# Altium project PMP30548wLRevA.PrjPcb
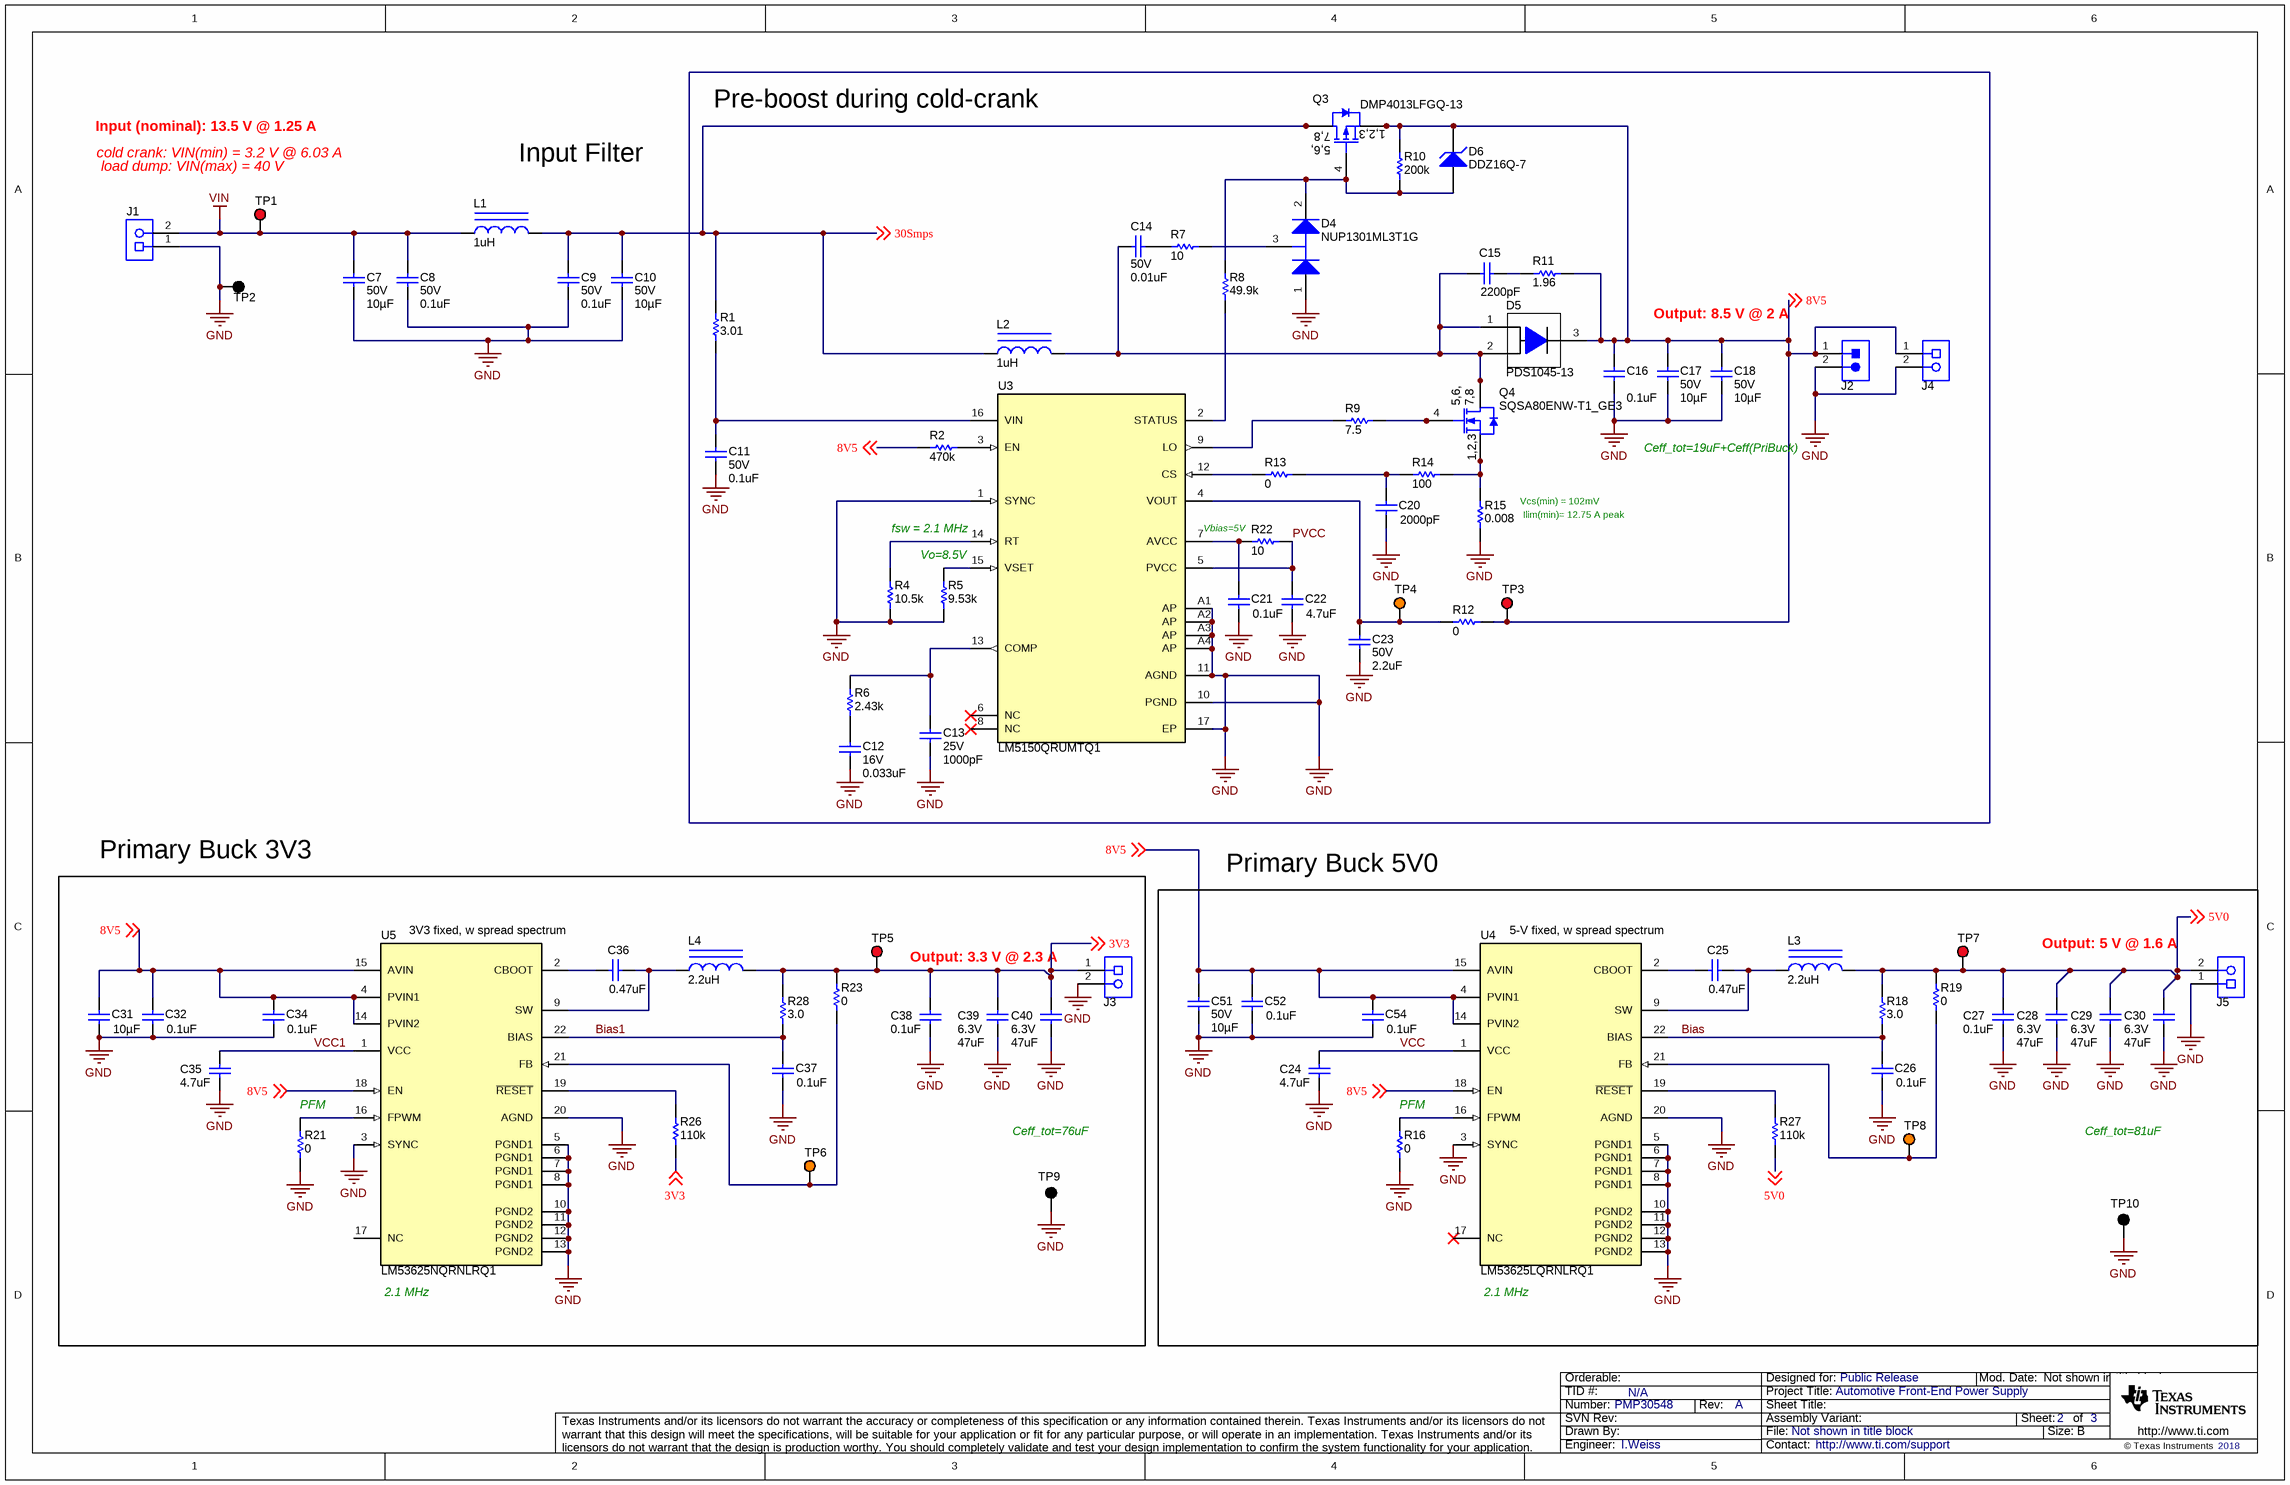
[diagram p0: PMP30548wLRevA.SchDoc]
TID: N/A; TechSupport: http://www.ti.com/support; SCH_Rev: A; PRJ_Title: Automotive Front-End Power Supply; PRJ_Number: PMP30548; PRJ_Engineer: I.Weiss; PRJ_Customer: Public Release; PCB_Rev: A; PCB_Layout: I.Weiss; CopyrightYear: 2018
2 sheets, 101 parts. Net scope: global (net labels, ports and power ports of the same name join across sheets).
Board file: PMP30548wLRevA.PcbDoc
Sheets:
  PMP30548wLRevA.SchDoc
  PMP30548wLRevA_Hardware.SchDoc

## Sheet PMP30548wLRevA.SchDoc
size 431 x 279 mm; Date: Not shown in title block; ApprovedBy: Not shown in title block; CheckedBy: Not shown in title block; Author: Not shown in title block; CompanyName: Not shown in title block; Engineer: Not shown in title block; Organization: Not shown in title block; Address1: Not shown in title block; Address2: Not shown in title block; Address3: Not shown in title block; Address4: Not shown in title block; DocumentNumber: 1; Revision: Use project parameter SCH_Rev; SheetNumber: 2; SheetTotal: 3; PageSetup: Record=PageOptions¦CenterHorizontal=True¦CenterVertical=True¦PrintScale=1.00¦XCorrection=1.00¦YCorrection=1.00¦PrintKind=0¦BorderSize=5000000¦LeftOffset=0¦BottomOffset=0¦Orientation=2¦PaperLength=1000¦PaperWidth=1000¦Scale=100¦PaperSource=15¦PrintQuality=600¦MediaType=1¦DitherType=10¦PaperKind=Letter¦PrintScaleMode=1

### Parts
C7  VDC_V: 50V  ValueDisplayed: 10µF  [1210_280]  (hidden comment: GRJ32ER71H106KE11L)
C8  VDC_V: 50V  ValueDisplayed: 0.1uF  [0603]  (hidden comment: GRM188R71H104KA93D)
C9  VDC_V: 50V  ValueDisplayed: 0.1uF  [0603]  (hidden comment: GRM188R71H104KA93D)
C10  VDC_V: 50V  ValueDisplayed: 10µF  [1210_280]  (hidden comment: GRJ32ER71H106KE11L)
C11  VDC_V: 50V  ValueDisplayed: 0.1uF  [0603]  (hidden comment: GRM188R71H104KA93D)
C12  VDC_V: 16V  ValueDisplayed: 0.033uF  [0402]  (hidden comment: GRM155R71C333KA01D)
C13  VDC_V: 25V  ValueDisplayed: 1000pF  [0402]  (hidden comment: C0402C102J3RACTU)
C14  VDC_V: 50V  ValueDisplayed: 0.01uF  [0402]  (hidden comment: GRM155R71H103KA88D)
C15  ValueDisplayed: 2200pF  [0402]  (hidden comment: GRM155R71H222KA01D)
C16  ValueDisplayed: 0.1uF  [0603]  (hidden comment: GRM188R71H104KA93D)
C17  VDC_V: 50V  ValueDisplayed: 10µF  [1210_280]  (hidden comment: GRJ32ER71H106KE11L)
C18  VDC_V: 50V  ValueDisplayed: 10µF  [1210_280]  (hidden comment: GRJ32ER71H106KE11L)
C20  ValueDisplayed: 2000pF  [0603]  (hidden comment: GRM188R71H202KA01D)
C21  ValueDisplayed: 0.1uF  [0603]  (hidden comment: GRM188R71H104KA93D)
C22  ValueDisplayed: 4.7uF  [0805_HV]  (hidden comment: 885012207025)
C23  VDC_V: 50V  ValueDisplayed: 2.2uF  [1206_180]  (hidden comment: C3216X7R1H225K160AB)
C24  ValueDisplayed: 4.7uF  [0805_HV]  (hidden comment: 885012207025)
C25  ValueDisplayed: 0.47uF  [0603]  (hidden comment: GRM188R71E474KA12D)
C26  ValueDisplayed: 0.1uF  [0603]  (hidden comment: GRM188R71H104KA93D)
C27  ValueDisplayed: 0.1uF  [0603]  (hidden comment: GRM188R71H104KA93D)
C28  VDC_V: 6.3V  ValueDisplayed: 47uF  [1210_280]  (hidden comment: GCM32ER70J476ME19L)
C29  VDC_V: 6.3V  ValueDisplayed: 47uF  [1210_280]  (hidden comment: GCM32ER70J476ME19L)
C30  VDC_V: 6.3V  ValueDisplayed: 47uF  [1210_280]  (hidden comment: GCM32ER70J476ME19L)
C31  ValueDisplayed: 10µF  [1210_280]  (hidden comment: GRJ32ER71H106KE11L)
C32  ValueDisplayed: 0.1uF  [0603]  (hidden comment: GRM188R71H104KA93D)
C34  ValueDisplayed: 0.1uF  [0603]  (hidden comment: GRM188R71H104KA93D)
C35  ValueDisplayed: 4.7uF  [0805_HV]  (hidden comment: 885012207025)
C36  ValueDisplayed: 0.47uF  [0603]  (hidden comment: GRM188R71E474KA12D)
C37  ValueDisplayed: 0.1uF  [0603]  (hidden comment: GRM188R71H104KA93D)
C38  ValueDisplayed: 0.1uF  [0603]  (hidden comment: GRM188R71H104KA93D)
C39  VDC_V: 6.3V  ValueDisplayed: 47uF  [1210_280]  (hidden comment: GCM32ER70J476ME19L)
C40  VDC_V: 6.3V  ValueDisplayed: 47uF  [1210_280]  (hidden comment: GCM32ER70J476ME19L)
C51  VDC_V: 50V  ValueDisplayed: 10µF  [1210_280]  (hidden comment: GRJ32ER71H106KE11L)
C52  ValueDisplayed: 0.1uF  [0603]  (hidden comment: GRM188R71H104KA93D)
C54  ValueDisplayed: 0.1uF  [0603]  (hidden comment: GRM188R71H104KA93D)
D4  NUP1301ML3T1G  [SOT-23]
D5  PDS1045-13  [POWERDI5]
D6  DDZ16Q-7  [SOD-123]
J1  691411510002  [Wurth_691411510002]  (value not drawn)
J2  PBC02SAAN  [Sullins_PBC02SAAN]  (value not drawn)
J3  691411510002  [Wurth_691411510002]  (value not drawn)
J4  691411510002  [Wurth_691411510002]  (value not drawn)
J5  691411510002  [Wurth_691411510002]  (value not drawn)
L1  ValueDisplayed: 1uH  [IHLP-2525CZ]  (hidden comment: IHLP2525CZER1R0M01)
L2  ValueDisplayed: 1uH  [IHLP-2525CZ]  (hidden comment: IHLP2525CZER1R0M01)
L3  ValueDisplayed: 2.2uH  [IHLP-1616BZ]  (hidden comment: IHLP1616BZER2R2M11)
L4  ValueDisplayed: 2.2uH  [IHLP-1616BZ]  (hidden comment: IHLP1616BZER2R2M11)
Q3  DMP4013LFGQ-13  [PowerDI3333-8]
Q4  SQSA80ENW-T1_GE3  [PowerPAK_1212-8]
R1  ValueDisplayed: 3.01  [0603]  (hidden comment: CRCW06033R01FKEA)
R2  ValueDisplayed: 470k  [0603]  (hidden comment: CRCW0603470KJNEA)
R4  ValueDisplayed: 10.5k  [0402]  (hidden comment: CRCW040210K5FKED)
R5  ValueDisplayed: 9.53k  [0603]  (hidden comment: RT0603BRD079K53L)
R6  ValueDisplayed: 2.43k  [0603]  (hidden comment: RG1608P-2431-B-T5)
R7  ValueDisplayed: 10  [0402]  (hidden comment: CRCW040210R0JNED)
R8  ValueDisplayed: 49.9k  [0603]  (hidden comment: CRCW060349K9FKEA)
R9  ValueDisplayed: 7.5  [0603]  (hidden comment: CRCW06037R50JNEA)
R10  ValueDisplayed: 200k  [0402]  (hidden comment: CRCW0402200KJNED)
R11  ValueDisplayed: 1.96  [0402]  (hidden comment: CRCW04021R96FKED)
R12  ValueDisplayed: 0  [0603]  (hidden comment: RCS06030000Z0EA)
R13  ValueDisplayed: 0  [0603]  (hidden comment: RCS06030000Z0EA)
R14  ValueDisplayed: 100  [0402]  (hidden comment: ERJ-2GEJ101X)
R15  ValueDisplayed: 0.008  [KRL2012]  (hidden comment: KRL2012M-R008-F-T1)
R16  ValueDisplayed: 0  [0402]  (hidden comment: CRCW04020000Z0EDHP)
R18  ValueDisplayed: 3.0  [0603]  (hidden comment: CRCW06033R00JNEA)
R19  ValueDisplayed: 0  [0402]  (hidden comment: CRCW04020000Z0EDHP)
R21  ValueDisplayed: 0  [0402]  (hidden comment: CRCW04020000Z0EDHP)
R22  ValueDisplayed: 10  [0603]  (hidden comment: CRCW060310R0JNEA)
R23  ValueDisplayed: 0  [0402]  (hidden comment: CRCW04020000Z0EDHP)
R26  ValueDisplayed: 110k  [0402]  (hidden comment: CRCW0402110KJNED)
R27  ValueDisplayed: 110k  [0402]  (hidden comment: CRCW0402110KJNED)
R28  ValueDisplayed: 3.0  [0603]  (hidden comment: CRCW06033R00JNEA)
TP1  5000  [Keystone5000]  (value not drawn)
TP2  5001  [Keystone5001]  (value not drawn)
TP3  5000  [Keystone5000]  (value not drawn)
TP4  5003  [Keystone5003]  (value not drawn)
TP5  5000  [Keystone5000]  (value not drawn)
TP6  5003  [Keystone5003]  (value not drawn)
TP7  5000  [Keystone5000]  (value not drawn)
TP8  5003  [Keystone5003]  (value not drawn)
TP9  5001  [Keystone5001]  (value not drawn)
TP10  5001  [Keystone5001]  (value not drawn)
U3  LM5150QRUMTQ1  [RUM0016C]
U4  LM53625LQRNLRQ1  [RNL0022A]
U5  LM53625NQRNLRQ1  [RNL0022A]

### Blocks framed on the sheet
Pre-boost during cold-crank: C11-C18 C20-C23 D4-D6 J2 J4 L2 Q3 Q4 R1 R2 R4-R15 R22 TP3 TP4 U3
Output: 3.3 V @ 2.3 A: C31 C32 C34-C40 J3 L4 R21 R23 R26 R28 TP5 TP6 TP9 U5
Output: 5 V @ 1.6 A: C24-C30 C51 C52 C54 J5 L3 R16 R18 R19 R27 TP7 TP8 TP10 U4

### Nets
GND: C7.2 C8.2 C9.2 C10.2 C11.2 C12.2 C13.2 C16.2 C17.2 C18.2 C20.2 C21.2 C22.2 C23.2 C24.2 C26.2 C27.2 C28.2 C29.2 C30.2 C31.2 C32.2 C34.2 C35.2 C37.2 C38.2 C39.2 C40.2 C51.2 C52.2 C54.2 D4.1(A) J1.1 J2.2 J3.2 J4.2 J5.1 R4.1 R5.1 R15.1 R16.1 R21.1 TP2.1 TP9.1 TP10.1 U3.1(SYNC) U3.10(PGND) U3.11(AGND) U3.17(EP) U3.A1(AP) U3.A2(AP) U3.A3(AP) U3.A4(AP) U4.3(SYNC) U4.5(PGND1) U4.6(PGND1) U4.7(PGND1) U4.8(PGND1) U4.10(PGND2) U4.11(PGND2) U4.12(PGND2) U4.13(PGND2) U4.20(AGND) U5.3(SYNC) U5.5(PGND1) U5.6(PGND1) U5.7(PGND1) U5.8(PGND1) U5.10(PGND2) U5.11(PGND2) U5.12(PGND2) U5.13(PGND2) U5.20(AGND)
VIN: C7.1 C8.1 J1.2 L1.1 TP1.1
3V3: C38.1 C39.1 C40.1 J3.1 L4.2 R23.2 R26.1 R28.2 TP5.1 ; off-sheet 3V3
5V0: C27.1 C28.1 C29.1 C30.1 J5.2 L3.2 R18.2 R19.2 R27.1 TP7.1 ; off-sheet 5V0
8V5: C16.1 C17.1 C18.1 C31.1 C32.1 C34.1 C51.1 C52.1 C54.1 D5.3(K) D6.1(K) J2.1 J4.1 Q3.1(S) Q3.2(S) Q3.3(S) R2.2 R10.2 R11.1 R12.1 TP3.1 U4.4(PVIN1) U4.14(PVIN2) U4.15(AVIN) U4.18(EN) U5.4(PVIN1) U5.14(PVIN2) U5.15(AVIN) U5.18(EN) ; off-sheet 8V5
30Smps: C9.1 C10.1 L1.2 L2.1 Q3.5(D) Q3.6(D) Q3.7(D) Q3.8(D) Q3.9(D) R1.2 ; off-sheet 30Smps
Bias: C26.1 R18.1 U4.22(BIAS)
Bias1: C37.1 R28.1 U5.22(BIAS)
PVCC: C22.1 R22.2 U3.5(PVCC)
VCC: C24.1 U4.1(VCC)
VCC1: C35.1 U5.1(VCC)
NetC11_1: C11.1 R1.1 U3.16(VIN)
NetC12_1: C12.1 R6.2
NetC13_1: C13.1 R6.1 U3.13(COMP)
NetC14_1: C14.1 C15.2 D5.1(A) D5.2(A) L2.2 Q4.5(D) Q4.6(D) Q4.7(D) Q4.8(D) Q4.9(D)
NetC14_2: C14.2 R7.2
NetC15_1: C15.1 R11.2
NetC20_1: C20.1 R13.1 R14.1
NetC21_1: C21.1 R22.1 U3.7(AVCC)
NetC23_1: C23.1 R12.2 TP4.1 U3.4(VOUT)
NetC25_1: C25.1 L3.1 U4.9(SW)
NetC25_2: C25.2 U4.2(CBOOT)
NetC36_1: C36.1 L4.1 U5.9(SW)
NetC36_2: C36.2 U5.2(CBOOT)
NetD4_2: D4.2(K) D6.2(A) Q3.4(G) R8.2 R10.1
NetD4_3: D4.3(C) R7.1
NetQ4_1: Q4.1(S) Q4.2(S) Q4.3(S) R14.2 R15.2
NetQ4_4: Q4.4(G) R9.2
NetR2_1: R2.1 U3.3(EN)
NetR4_2: R4.2 U3.14(RT)
NetR5_2: R5.2 U3.15(VSET)
NetR8_1: R8.1 U3.2(STATUS)
NetR9_1: R9.1 U3.9(LO)
NetR13_2: R13.2 U3.12(CS)
NetR16_2: R16.2 U4.16(FPWM)
NetR19_1: R19.1 TP8.1 U4.21(FB)
NetR21_2: R21.2 U5.16(FPWM)
NetR23_1: R23.1 TP6.1 U5.21(FB)
NetR26_2: R26.2 U5.19(~{RESET})
NetR27_2: R27.2 U4.19(~{RESET})

Not connected (* = marked no-connect by the designer): U3 6(NC)* 8(NC)*; U4 17(NC)*; U5 17(NC)

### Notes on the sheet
- load dump: VIN(max) = 40 V
- Input (nominal): 13.5 V @ 1.25 A
- cold crank: VIN(min) = 3.2 V @ 6.03 A
- Input Filter
- Output: 8.5 V @ 2 A
- (near R15) Vcs(min) = 102mV
- Ceff_tot=19uF+Ceff(PriBuck)
- (near U3) fsw = 2.1 MHz
- Vo=8.5V
- (near R22) Vbias=5V
- (near R15) Ilim(min)= 12.75 A peak
- Primary Buck 3V3
- Primary Buck 5V0
- 3V3 fixed, w spread spectrum
- 5-V fixed, w spread spectrum
- (near R21) PFM
- (near R16) PFM
- Ceff_tot=76uF
- Ceff_tot=81uF
- (near U5) 2.1 MHz
- (near U4) 2.1 MHz

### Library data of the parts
C7 C10 C17 C18 C51 = CMP-0081135-1: CAP, CERM, 10 µF, 50 V,+/- 10%, X7R, 1210; Manufacturer: MuRata; TaMin_C: -55°C; ESR_ohm: 1m; Polarized: N; SizeAreaWB_mm2: 14.7; Value1: 0.001 ohm; U/M: EA; Value: 10uF; TaMax_C: 125°C; SizeZ_mm: 2.8; SizeX_mm: 3.2; SizeY_mm: 2.5; Cap_Case: 1210; SizeArea_mm2: 8; CompType: Capacitor; AEC Category: Q200
C8 C9 C11 = CMP-0007434-4: CAP, CERM, 0.1 uF, 50 V, +/- 10%, X7R, 0603; Manufacturer: MuRata; TaMin_C: -55°C; Polarized: N; SizeAreaWB_mm2: 4.68; Value1: Unknown; U/M: EA; Value: 0.1uF; TaMax_C: 125°C; SizeZ_mm: 1; SizeX_mm: 1.6; SizeY_mm: 0.8; SizeArea_mm2: 1.28; CompType: Capacitor; Cap_F: 100nF; AEC Category: Q200
C12 = CMP-0006650-2: CAP, CERM, 0.033 uF, 16 V, +/- 10%, X7R, 0402; Manufacturer: MuRata; TaMin_C: -55°C; Polarized: N; SizeAreaWB_mm2: 3; Value1: Unknown; U/M: EA; TaMax_C: 125°C; SizeZ_mm: 0.6; SizeX_mm: 1; SizeY_mm: 0.5; Cap_F: 33nF; AEC Category: Q200
C13 = CMP-0006234-2: CAP, CERM, 1000 pF, 25 V, +/- 5%, X7R, 0402; Manufacturer: Kemet; TaMin_C: -55°C; Polarized: N; SizeAreaWB_mm2: 3; Value1: Unknown; U/M: EA; Value: 1000pF; TaMax_C: 125°C; SizeZ_mm: 0.6; SizeX_mm: 1; SizeY_mm: 0.5; Cap_F: 1nF; AEC Category: Q200
C14 = CMP-0006674-2: CAP, CERM, 0.01 uF, 50 V, +/- 10%, X7R, 0402; Manufacturer: MuRata; TaMin_C: -55°C; Polarized: N; SizeAreaWB_mm2: 3; Value1: Unknown; U/M: EA; Value: 0.01uF; TaMax_C: 125°C; SizeZ_mm: 0.6; SizeX_mm: 1; SizeY_mm: 0.5; Cap_F: 10nF; AEC Category: Q200
C15 = CMP-0006683-2: CAP, CERM, 2200 pF, 50 V, +/- 10%, X7R, 0402; Manufacturer: MuRata; TaMin_C: -55°C; Polarized: N; SizeAreaWB_mm2: 3; Value1: Unknown; U/M: EA; Value: 2200pF; TaMax_C: 125°C; SizeZ_mm: 0.6; SizeX_mm: 1; SizeY_mm: 0.5; Value2: 50V; CompType: Capacitor; Cap_F: 2.2nF; AEC Category: Q200
C16 C21 C26 C27 C32 C34 C37 C38 C52 C54 = CMP-0007434-4: CAP, CERM, 0.1 uF, 50 V, +/- 10%, X7R, 0603; Manufacturer: MuRata; TaMin_C: -55°C; Polarized: N; SizeAreaWB_mm2: 4.68; Value1: Unknown; U/M: EA; Value: 0.1uF; TaMax_C: 125°C; SizeZ_mm: 1; SizeX_mm: 1.6; SizeY_mm: 0.8; Value2: 50V; SizeArea_mm2: 1.28; CompType: Capacitor; Cap_F: 100nF; AEC Category: Q200
C20 = CMP-0007441-5: CAP, CERM, 2000 pF, 50 V, +/- 10%, X7R, 0603; Manufacturer: MuRata; TaMin_C: -55°C; Polarized: N; SizeAreaWB_mm2: 4.68; Value1: Unknown; U/M: EA; Value: 2000pF; TaMax_C: 125°C; SizeZ_mm: 1; SizeX_mm: 1.6; SizeY_mm: 0.8; Value2: 50V; SizeArea_mm2: 1.28; CompType: Capacitor; Cap_F: 2nF; AEC Category: Q200
C22 C24 C35 = CMP-0007690-2: CAP, CERM, 4.7 uF, 10 V, +/- 10%, X7R, 0805; Manufacturer: Wurth Elektronik; TaMin_C: -55°C; Polarized: N; SizeAreaWB_mm2: 6.75; Value1: Unknown; U/M: EA; Value: 4.7uF; TaMax_C: 125°C; SizeZ_mm: 1.45; SizeX_mm: 2; SizeY_mm: 1.25; Cap_Case: 0805; Value2: 10V; SizeArea_mm2: 2.5; CompType: Capacitor; Cap_F: 4.7µF; AEC Category: Q200
C23 = CMP-0008698-2: CAP, CERM, 2.2 uF, 50 V, +/- 10%, X7R, 1206; Manufacturer: TDK; TaMin_C: -55°C; ESR_ohm: 5.887m; Polarized: N; SizeAreaWB_mm2: 10.92; Value1: 0.005887 ohm; U/M: EA; Value: 2.2uF; TaMax_C: 125°C; SizeZ_mm: 1.8; SizeX_mm: 3.2; SizeY_mm: 1.6; SizeArea_mm2: 5.12; CompType: Capacitor; Cap_F: 2.2µF; IRMS_A: 2.99226A; AEC Category: Q200
C25 C36 = CMP-0007424-4: CAP, CERM, 0.47 uF, 25 V, +/- 10%, X7R, 0603; Manufacturer: MuRata; TaMin_C: -55°C; Polarized: N; SizeAreaWB_mm2: 4.68; Value1: Unknown; U/M: EA; Value: 0.47uF; TaMax_C: 125°C; SizeZ_mm: 1; SizeX_mm: 1.6; SizeY_mm: 0.8; Value2: 25V; SizeArea_mm2: 1.28; CompType: Capacitor; Cap_F: 470nF; AEC Category: Q200
C28-C30 C39 C40 = CMP-0009173-2: CAP, CERM, 47 uF, 6.3 V, +/- 20%, X7R, 1210; Manufacturer: MuRata; TaMin_C: -55°C; Polarized: N; SizeAreaWB_mm2: 14.7; Value1: Unknown; U/M: EA; Value: 47uF; TaMax_C: 125°C; SizeZ_mm: 2.8; SizeX_mm: 3.2; SizeY_mm: 2.5; Cap_Case: 1210; SizeArea_mm2: 8; CompType: Capacitor; Cap_F: 47µF; AEC Category: Q200
C31 = CMP-0081135-1: CAP, CERM, 10 µF, 50 V,+/- 10%, X7R, 1210; Manufacturer: MuRata; TaMin_C: -55°C; ESR_ohm: 1m; Polarized: N; SizeAreaWB_mm2: 14.7; Value1: 0.001 ohm; U/M: EA; Value: 10uF; TaMax_C: 125°C; SizeZ_mm: 2.8; SizeX_mm: 3.2; SizeY_mm: 2.5; Cap_Case: 1210; Value2: 50V; SizeArea_mm2: 8; CompType: Capacitor; AEC Category: Q200
D4 = CMP-0029164-1: Diode, Standard Recovery Rectifier, 70 V, 0.215 A, AEC-Q101, SOT-23; Manufacturer: ON Semiconductor; Io_A: 2.15dA; Green_Lifecycle: Not Set; SizeAreaWB_mm2: 14; Vr_V: 70V; Green_REACh: Incomplete; Value1: 0.215A; TJmax_C: 150°C; U/M: EA; Value: 70V; SizeZ_mm: 1.1; SizeX_mm: 2.5; SizeY_mm: 3; Vf_V: 1.25V; SizeArea_mm2: 7.5; AEC Qualified: Y; AEC Category: Q101
D5 = CMP-0028629-2: Diode, Schottky, 45 V, 10 A, PowerDI5; Manufacturer: Diodes Inc.; Io_A: 10A; Green_Lifecycle: Not Set; SizeAreaWB_mm2: 49.56; Vr_V: 45V; Green_REACh: Incomplete; TJmax_C: 150°C; Value: 45V; SizeZ_mm: 1.05; SizeX_mm: 6.4; SizeY_mm: 3.9; Vf_V: 510mV; Value2: 0.51V; SizeArea_mm2: 24.96; AEC Category: Q101; RJC_CperW: 85
D6 = CMP-0005774-2: Diode, Zener, 16 V, 310 mW, AEC-Q101, SOD-123; Manufacturer: Diodes Inc.; Power_W: 310mW; SizeAreaWB_mm2: 13.095; Vz_V: 16V; Value1: 0.31W; RJA_CperW: 403; U/M: EA; Value: 16V; SizeZ_mm: 1.35; SizeX_mm: 3.85; SizeY_mm: 1.7; SizeArea_mm2: 6.545; AEC Qualified: Y; AEC Category: Q101
J1 J3-J5 = CMP-0054827-2: Receptacle, 5.08mm, 2x1, INOX Steel, R/A, TH; Manufacturer: Wurth Elektronik; CompType: Terminal Block; Row_Count: 1; Cert_CULUS: Y; CNHeader: FALSE; Gender: Female; Current_A: 10A; Pitch_mm: 5.08; CT: TRUE
J2 = CMP-0054566-1: Header, 100mil, 2x1, Gold, TH; Manufacturer: Sullins Connector Solutions; CNHeader: TRUE; Current_A: 3A; Green_Lifecycle: Active; Shrouded: N; Gender: Male; Green_REACh: Passed; Voltage_V: 1.8kV; Row_Count: 1; Pitch_mm: 2.54; CT: FALSE; Cert_UL: Y
L1 L2 = CMP-0063376-1: Inductor, Shielded Drum Core, Powdered Iron, 1 uH, 11 A, 0.009 ohm, SMD; Manufacturer: Vishay-Dale; Isat: 22A @ 20% inductance drop; Irms: 11A @ 40C rise; Green_Lifecycle: Active; SizeAreaWB_mm2: 75.0442; DCR_ohm: 9m; Green_REACh: Passed; Value: 1uH; Imax_A: 11A; SizeZ_mm: 3; SizeX_mm: 6.86; SizeY_mm: 6.47; SizeArea_mm2: 44.3842; Ind_H: 1µH; AEC Category: Q200
L3 L4 = CMP-0063279-1: Inductor, Shielded Drum Core, Powdered Iron, 2.2 uH, 3.25 A, 0.061 ohm, SMD; Manufacturer: Vishay-Dale; Isat: 3.25A @ 20% inductance drop; Irms: 3.25A @ 40C rise; Green_Lifecycle: Active; SizeAreaWB_mm2: 27.577; DCR_ohm: 0.061; Green_REACh: Passed; Value: 2.2uH; Imax_A: 3.25A; SizeZ_mm: 2; SizeX_mm: 4.45; SizeY_mm: 4.06; SizeArea_mm2: 18.067; Ind_H: 2.2µH; AEC Category: Q200
Q3 = CMP-0067588-1: MOSFET, P-CH, -40 V, -10.3 A, AEC-Q101, 8-PowerVDFN; Alternate Manufacturer: None; Manufacturer: Diodes Inc.; Rdson45_ohm: 0.018; QgTyp_nC: 32.5; SizeAreaWB_mm2: 18.49; Vgs_V: -20V; Value1: 0.018 ohm; VdsMax_V: -40V; U/M: EA; Value: -40V; IdsMax_A: -10.3A; SizeZ_mm: 0.8; SizeX_mm: 3.3; Value2: 32.5 nC; SizeArea_mm2: 10.89; ChType: P; AEC Qualified: Y; AEC Category: Q101
Q4 = CMP-0750014-1: MOSFET, N-CH, 80 V, 18 A, AEC-Q101, PowerPAK 1212; Alternate Manufacturer: None; Manufacturer: Vishay-Siliconix; Rdson45_ohm: 0.027; QgTyp_nC: 17; AEC Category: Q101; SizeArea_mm2: 10.89; SizeAreaWB_mm2: 18.49; Value: 80V; Vgs_V: 20V; SizeX_mm: 3.3; Value2: 17 nC; ChMode: Enhancement; AEC Qualified: Y; Value1: 0.027 ohm; SizeZ_mm: 1.04; IdsMax_A: 18A; ChType: N
R1 = CMP-0022396-4: RES, 3.01, 1%, 0.1 W, AEC-Q200 Grade 0, 0603; Manufacturer: Vishay-Dale; Power_W: 100mW; TempCo: 100 ppm/C; Value_Code: 3R01; Value: 3.01; EIA_Code: E96; SizeX_mm: 1.6; SizeY_mm: 0.8; SizeZ_mm: 1; Value2: 0.1W; SizeArea_mm2: 1.28; CompType: Resistor; AEC Qualified: Y; VDC_V: 75V; AEC Category: Q200; AEC Grade: 0
R2 = CMP-0025812-4: RES, 470 k, 5%, 0.1 W, AEC-Q200 Grade 0, 0603; Manufacturer: Vishay-Dale; Power_W: 100mW; TempCo: 200 ppm/C; Value: 470k; EIA_Code: E24; SizeX_mm: 1.6; SizeY_mm: 0.8; SizeZ_mm: 1; Value2: 0.1W; SizeArea_mm2: 1.28; CompType: Resistor; AEC Qualified: Y; VDC_V: 75V; AEC Category: Q200; AEC Grade: 0
R4 = CMP-0025960-3: RES, 10.5 k, 1%, 0.063 W, AEC-Q200 Grade 0, 0402; Manufacturer: Vishay-Dale; Power_W: 63mW; TempCo: 100 ppm/C; Value_Code: 10k5; Value: 10.5k; EIA_Code: E96; SizeX_mm: 1; SizeY_mm: 0.5; SizeZ_mm: 0.6; Value2: 0.063W; CompType: Resistor; AEC Qualified: Y; VDC_V: 50V; AEC Category: Q200; AEC Grade: 0
R5 = CMP-0024555-2: RES, 9.53 k, 0.1%, 0.1 W, 0603; Manufacturer: Yageo America; Power_W: 100mW; TempCo: 25 ppm/C; Value_Code: 9k53; U/M: EA; Value: 9.53k; EIA_Code: E192; SizeX_mm: 1.6; SizeY_mm: 0.8; SizeZ_mm: 1; Value2: 0.1W; SizeArea_mm2: 1.28; CompType: Resistor; VDC_V: 75V; AEC Category: Q200
R6 = CMP-0023484-3: RES, 2.43 k, 0.1%, 0.1 W, 0603; Manufacturer: Susumu Co Ltd; Value_Code: 2k43; SizeArea_mm2: 1.28; AEC Category: Q200; Value: 2.43k; SizeZ_mm: 1; SizeY_mm: 0.8; Power_W: 100mW; Value2: 0.1W; CompType: Resistor; SizeX_mm: 1.6; EIA_Code: E192; TempCo: 25 ppm/C; VDC_V: 75V; U/M: EA
R7 = CMP-0026827-3: RES, 10, 5%, 0.063 W, AEC-Q200 Grade 0, 0402; Manufacturer: Vishay-Dale; Power_W: 63mW; TempCo: 200 ppm/C; Value_Code: 10R0; Value: 10; EIA_Code: E24; SizeX_mm: 1; SizeY_mm: 0.5; SizeZ_mm: 0.6; Value2: 0.063W; AEC Qualified: Y; VDC_V: 50V; AEC Category: Q200; AEC Grade: 0
R8 = CMP-0022447-4: RES, 49.9 k, 1%, 0.1 W, AEC-Q200 Grade 0, 0603; Manufacturer: Vishay-Dale; Power_W: 100mW; TempCo: 100 ppm/C; Value_Code: 49k9; Value: 49.9k; EIA_Code: E96; SizeX_mm: 1.6; SizeY_mm: 0.8; SizeZ_mm: 1; Value2: 0.1W; SizeArea_mm2: 1.28; CompType: Resistor; AEC Qualified: Y; VDC_V: 75V; AEC Category: Q200; AEC Grade: 0
R9 = CMP-0025857-4: RES, 7.5, 5%, 0.1 W, AEC-Q200 Grade 0, 0603; Manufacturer: Vishay-Dale; Power_W: 100mW; TempCo: 200 ppm/C; Value_Code: 7R50; Value: 7.5; EIA_Code: E24; SizeX_mm: 1.6; SizeY_mm: 0.8; SizeZ_mm: 1; Value2: 0.1W; SizeArea_mm2: 1.28; CompType: Resistor; AEC Qualified: Y; VDC_V: 75V; AEC Category: Q200; AEC Grade: 0
R10 = CMP-0026873-2: RES, 200 k, 5%, 0.063 W, AEC-Q200 Grade 0, 0402; Manufacturer: Vishay-Dale; Power_W: 63mW; TempCo: 200 ppm/C; Value: 200k; EIA_Code: E24; SizeX_mm: 1; SizeY_mm: 0.5; SizeZ_mm: 0.6; Value2: 0.063W; CompType: Resistor; AEC Qualified: Y; VDC_V: 50V; AEC Category: Q200; AEC Grade: 0
R11 = CMP-0026157-2: RES, 1.96, 1%, 0.063 W, AEC-Q200 Grade 0, 0402; Manufacturer: Vishay-Dale; Power_W: 63mW; TempCo: 100 ppm/C; Value_Code: 1R96; Value: 1.96; EIA_Code: E96; SizeX_mm: 1; SizeY_mm: 0.5; SizeZ_mm: 0.6; Value2: 0.063W; AEC Qualified: Y; VDC_V: 50V; AEC Category: Q200; AEC Grade: 0
R12 R13 = CMP-0081973-1: RES, 0, 0%, 0.25 W, AEC-Q200 Grade 0, 0603; Manufacturer: Vishay-Dale; SizeAreaWB_mm2: 4.68; SizeArea_mm2: 1.28; AEC Qualified: Y; AEC Category: Q200; Value: 0; SizeZ_mm: 1; SizeY_mm: 0.8; Power_W: 250mW; Value2: 0.25W; CompType: Resistor; SizeX_mm: 1.6
R14 = CMP-0026993-2: RES, 100, 5%, 0.1 W, AEC-Q200 Grade 0, 0402; Manufacturer: Panasonic; Power_W: 100mW; TempCo: 200 ppm/C; Value_Code: 100R; U/M: EA; Value: 100; EIA_Code: E24; SizeX_mm: 1; SizeY_mm: 0.5; SizeZ_mm: 0.6; Value2: 0.1W; CompType: Resistor; AEC Qualified: Y; AEC Grade: 0; AEC Category: Q200
R15 = CMP-0015103-2: RES, 0.008, 1%, 1 W, AEC-Q200 Grade 0, 0508; Manufacturer: Susumu Co Ltd; Power_W: 1W; TempCo: 25 ppm/C; Value_Code: 8L000; U/M: EA; Value: 0.008; EIA_Code: E96; Res_ohm: 8m; CompType: Resistor; AEC Qualified: Y; AEC Grade: 0; AEC Category: Q200
R16 R19 R21 R23 = CMP-0081856-1: RES, 0, 0%, 0.2 W, AEC-Q200 Grade 0, 0402; Manufacturer: Vishay-Dale; SizeAreaWB_mm2: 3; SizeArea_mm2: 0.5; AEC Qualified: Y; AEC Category: Q200; Value: 0; SizeZ_mm: 0.6; Power_W: 200mW; VDC_V: 50V; Value2: 0.2W; CompType: Resistor; SizeX_mm: 1
R18 R28 = CMP-0025804-4: RES, 3.0, 5%, 0.1 W, AEC-Q200 Grade 0, 0603; Manufacturer: Vishay-Dale; Power_W: 100mW; TempCo: 200 ppm/C; Value_Code: 3R00; Value: 3.0; EIA_Code: E24; Res_ohm: 3; SizeX_mm: 1.6; SizeY_mm: 0.8; SizeZ_mm: 1; Value2: 0.1W; SizeArea_mm2: 1.28; CompType: Resistor; AEC Qualified: Y; VDC_V: 75V; AEC Category: Q200; AEC Grade: 0
R22 = CMP-0025703-4: RES, 10, 5%, 0.1 W, AEC-Q200 Grade 0, 0603; Manufacturer: Vishay-Dale; Power_W: 100mW; TempCo: 200 ppm/C; Value_Code: 10R0; Value: 10; EIA_Code: E24; SizeX_mm: 1.6; SizeY_mm: 0.8; SizeZ_mm: 1; Value2: 0.1W; SizeArea_mm2: 1.28; CompType: Resistor; AEC Qualified: Y; VDC_V: 75V; AEC Category: Q200; AEC Grade: 0
R26 R27 = CMP-0026828-2: RES, 110 k, 5%, 0.063 W, AEC-Q200 Grade 0, 0402; Manufacturer: Vishay-Dale; Power_W: 63mW; TempCo: 200 ppm/C; Value: 110k; EIA_Code: E24; SizeX_mm: 1; SizeY_mm: 0.5; SizeZ_mm: 0.6; Value2: 0.063W; CompType: Resistor; AEC Qualified: Y; VDC_V: 50V; AEC Category: Q200; AEC Grade: 0
TP1 TP3 TP5 TP7 = CMP-0055137-1: Test Point, Miniature, Red, TH; Manufacturer: Keystone; CNHeader: FALSE; Green_Lifecycle: Active; Green_REACh: Passed; ContactFinish: Silver; CT: TRUE
TP2 TP9 TP10 = CMP-0055138-1: Test Point, Miniature, Black, TH; Manufacturer: Keystone; CNHeader: FALSE; Green_Lifecycle: Active; Green_REACh: Passed; ContactFinish: Silver; CT: TRUE
TP4 TP6 TP8 = CMP-0055140-1: Test Point, Miniature, Orange, TH; Manufacturer: Keystone; CNHeader: FALSE; Green_Lifecycle: Active; Green_REACh: Passed; ContactFinish: Silver; CT: TRUE
U3 = CMP-0078203-1: Wide VIN Automotive Low IQ Boost Controller, RUM0016C (WQFN-16); Alternate PartNumber: LM5150QRUMRQ1; Alternate Manufacturer: Texas Instruments; SizeAreaWB_mm2: 25; SizeZ_mm: 0.8; SizeX_mm: 4; SizeArea_mm2: 16; CompType: IC; AEC Qualified: Y; AEC Category: Q200
U4 = CMP-0076349-4: 2.5A, 36 V Synchronous, 2.1MHz, Automotive Step Down DC-DC Converter, RNL0022A (VQFN-HR-22); Manufacturer: Texas Instruments; Alternate PartNumber: LM53625LQRNLTQ1; SizeX_mm: 4.0; SizeY_mm: 5.0; CompType: IC; SizeZ_mm: 0.9; SizeArea_mm2: 20.0; SizeAreaWB_mm2: 42.0; AEC Category: Q200; AEC Qualified: Y
U5 = CMP-0076351-4: 2.5A, 36 V Synchronous, 2.1MHz, Automotive Step Down DC-DC Converter, RNL0022A (VQFN-HR-22); Manufacturer: Texas Instruments; Alternate PartNumber: LM53625NQRNLTQ1; SizeX_mm: 4.0; SizeY_mm: 5.0; CompType: IC; SizeZ_mm: 0.9; SizeArea_mm2: 20.0; SizeAreaWB_mm2: 42.0; AEC Category: Q200; AEC Qualified: Y

## Sheet PMP30548wLRevA_Hardware.SchDoc
size 431 x 279 mm; Date: Not shown in title block; ApprovedBy: Not shown in title block; CheckedBy: Not shown in title block; Author: Not shown in title block; CompanyName: Not shown in title block; Engineer: Not shown in title block; Organization: Not shown in title block; Address1: Not shown in title block; Address2: Not shown in title block; Address3: Not shown in title block; Address4: Not shown in title block; DocumentNumber: 1; Revision: Use project parameter SCH_Rev; SheetNumber: 3; SheetTotal: 3; PageSetup: Record=PageOptions¦CenterHorizontal=True¦CenterVertical=True¦PrintScale=1.00¦XCorrection=1.00¦YCorrection=1.00¦PrintKind=0¦BorderSize=5000000¦LeftOffset=0¦BottomOffset=0¦Orientation=2¦PaperLength=1000¦PaperWidth=1000¦Scale=100¦PaperSource=15¦PrintQuality=600¦MediaType=1¦DitherType=10¦PaperKind=Letter¦PrintScaleMode=1
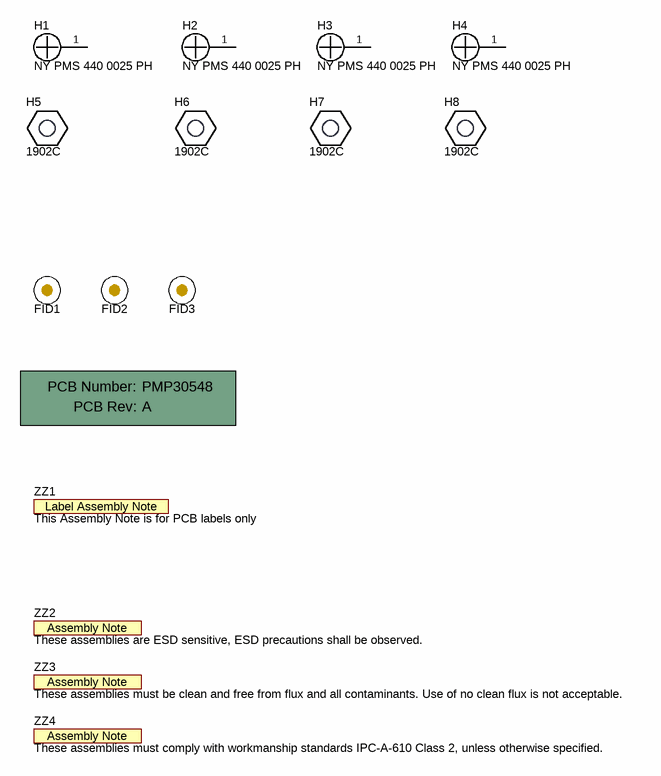
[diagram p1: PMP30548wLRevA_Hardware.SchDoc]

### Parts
!PCB  Printed Circuit Board  (value not drawn)  (mechanical)
FID1  Fiducial  [Fiducial10-20]  (value not drawn)
FID2  Fiducial  [Fiducial10-20]  (value not drawn)
FID3  Fiducial  [Fiducial10-20]  (value not drawn)
H1  NY PMS 440 0025 PH  [NY PMS 440 0025 PH]
H2  NY PMS 440 0025 PH  [NY PMS 440 0025 PH]
H3  NY PMS 440 0025 PH  [NY PMS 440 0025 PH]
H4  NY PMS 440 0025 PH  [NY PMS 440 0025 PH]
H5  1902C  [Keystone_1902C]
H6  1902C  [Keystone_1902C]
H7  1902C  [Keystone_1902C]
H8  1902C  [Keystone_1902C]
ZZ1  This Assembly Note is for PCB labels only  [AssemblyNoteLabel]  (no BOM)
ZZ2  These assemblies are ESD sensitive, ESD precautions shall be observed.  [AssemblyNote]  (no BOM)
ZZ3  These assemblies must be clean and free from flux and all contaminants. Use of no clean flux is not acceptable.  [AssemblyNote]  (no BOM)
ZZ4  These assemblies must comply with workmanship standards IPC-A-610 Class 2, unless otherwise specified.  [AssemblyNote]  (no BOM)

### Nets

Not connected (* = marked no-connect by the designer): H1 1; H2 1; H3 1; H4 1

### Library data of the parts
!PCB = CMP-0003618-2: Manufacturer: Any; PartNumber: PMP30548
FID1-FID3 = CMP-0077181-1: Fiducial mark.  There is nothing to buy or mount.
H1-H4 = CMP-0003617-1: Machine Screw, Round, #4-40 x 1/4, Nylon, Philips panhead; Manufacturer: B&F Fastener Supply; CompType: Hardware
H5-H8 = CMP-0003610-1: Standoff, Hex, 0.5"L #4-40 Nylon; Manufacturer: Keystone; CompType: Hardware
ZZ1 = CMP-0003616-3
ZZ2 = CMP-0077236-1
ZZ3 = CMP-0077237-1
ZZ4 = CMP-0077238-1

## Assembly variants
001: all parts fitted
